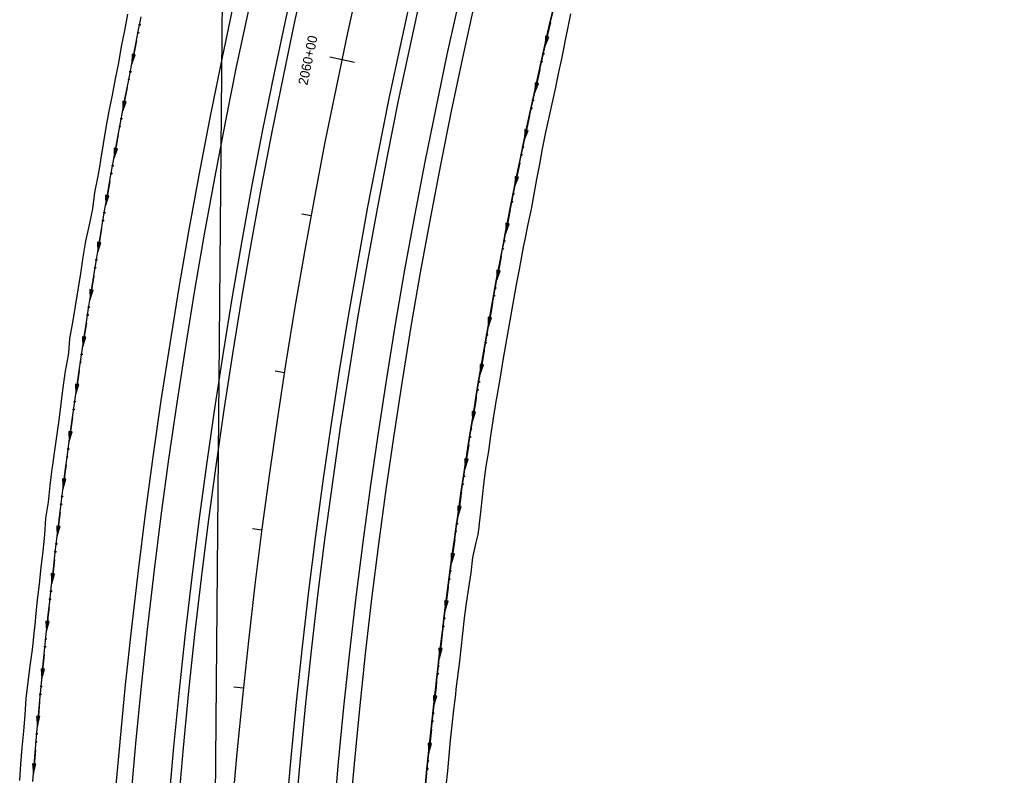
# Model space of a CAD drawing. Extents: x 1611108 to 1749517, y 619561 to 797725.
# Drawn here: x 1713487 to 1714111, y 762566 to 763041 of the extents above; entities that cross this region are included whole.
import ezdxf

# ---------------------------------------------------------------- set-up
doc = ezdxf.new("R2010")
doc.units = 0
for name, color, linetype in [('R_Ditch', 7, 'Continuous'), ('R_Horz Alg', 7, 'Continuous'), ('R_Horz Alg Annot', 7, 'Continuous'), ('R_Horz Alg Stationing', 7, 'Continuous'), ('R_Proposed Const Limits', 7, 'Continuous'), ('R_Proposed Road', 7, 'Continuous')]:
    doc.layers.add(name, color=color, linetype=linetype)

msp = doc.modelspace()

# ---------------------------------------------------------------- linework, layer by layer
at = {"layer": 'R_Ditch'}
for p, q in [((1713817.4, 763030.58), (1713817.11, 763024.49)), ((1713817.11, 763024.49), (1713819.47, 763030.11)), ((1713819.47, 763030.11), (1713817.4, 763030.58)), ((1713557.34, 763019.3), (1713557.21, 763013.21)), ((1713557.21, 763013.21), (1713559.41, 763018.89)), ((1713559.41, 763018.89), (1713557.34, 763019.3)), ((1713810.81, 763001.26), (1713810.56, 762995.18)), ((1713810.56, 762995.18), (1713812.87, 763000.81)), ((1713812.87, 763000.81), (1713810.81, 763001.26)), ((1713551.58, 762989.81), (1713551.5, 762983.72)), ((1713551.5, 762983.72), (1713553.66, 762989.42)), ((1713553.66, 762989.42), (1713551.58, 762989.81)), ((1713804.45, 762971.9), (1713804.24, 762965.81)), ((1713804.24, 762965.81), (1713806.52, 762971.46)), ((1713806.52, 762971.46), (1713804.45, 762971.9)), ((1713546.06, 762960.28), (1713546.02, 762954.19)), ((1713546.02, 762954.19), (1713548.14, 762959.9)), ((1713548.14, 762959.9), (1713546.06, 762960.28)), ((1713798.33, 762942.48), (1713798.17, 762936.39)), ((1713798.17, 762936.39), (1713800.4, 762942.06)), ((1713800.4, 762942.06), (1713798.33, 762942.48)), ((1713542.84, 762930.34), (1713540.75, 762930.71)), ((1713540.75, 762930.71), (1713540.77, 762924.61)), ((1713540.77, 762924.61), (1713542.84, 762930.34)), ((1713792.44, 762913.02), (1713792.34, 762906.93)), ((1713792.34, 762906.93), (1713794.52, 762912.61)), ((1713794.52, 762912.61), (1713792.44, 762913.02)), ((1713537.76, 762900.75), (1713535.68, 762901.09)), ((1713535.68, 762901.09), (1713535.74, 762895)), ((1713535.74, 762895), (1713537.76, 762900.75)), ((1713786.8, 762883.51), (1713786.74, 762877.41)), ((1713786.74, 762877.41), (1713788.88, 762883.12)), ((1713788.88, 762883.12), (1713786.8, 762883.51)), ((1713532.91, 762871.11), (1713530.82, 762871.44)), ((1713530.82, 762871.44), (1713530.93, 762865.35)), ((1713530.93, 762865.35), (1713532.91, 762871.11)), ((1713781.4, 762853.95), (1713781.39, 762847.86)), ((1713781.39, 762847.86), (1713783.48, 762853.58)), ((1713783.48, 762853.58), (1713781.4, 762853.95)), ((1713528.29, 762841.44), (1713526.2, 762841.75)), ((1713526.2, 762841.75), (1713526.35, 762835.66)), ((1713526.35, 762835.66), (1713528.29, 762841.44)), ((1713778.32, 762823.99), (1713776.24, 762824.35)), ((1713776.24, 762824.35), (1713776.27, 762818.26)), ((1713776.27, 762818.26), (1713778.32, 762823.99)), ((1713523.9, 762811.73), (1713521.8, 762812.03)), ((1713521.8, 762812.03), (1713521.99, 762805.94)), ((1713521.99, 762805.94), (1713523.9, 762811.73)), ((1713773.4, 762794.37), (1713771.31, 762794.71)), ((1713771.31, 762794.71), (1713771.4, 762788.62)), ((1713771.4, 762788.62), (1713773.4, 762794.37)), ((1713519.73, 762781.99), (1713517.63, 762782.28)), ((1713517.63, 762782.28), (1713517.87, 762776.19)), ((1713517.87, 762776.19), (1713519.73, 762781.99)), ((1713768.72, 762764.71), (1713766.62, 762765.03)), ((1713766.62, 762765.03), (1713766.77, 762758.94)), ((1713766.77, 762758.94), (1713768.72, 762764.71)), ((1713515.78, 762752.22), (1713513.69, 762752.49)), ((1713513.69, 762752.49), (1713513.97, 762746.4)), ((1713513.97, 762746.4), (1713515.78, 762752.22)), ((1713764.28, 762735.01), (1713762.19, 762735.31)), ((1713762.19, 762735.31), (1713762.38, 762729.22)), ((1713762.38, 762729.22), (1713764.28, 762735.01)), ((1713512.07, 762722.42), (1713509.97, 762722.68)), ((1713509.97, 762722.68), (1713510.3, 762716.59)), ((1713510.3, 762716.59), (1713512.07, 762722.42)), ((1713760.08, 762705.28), (1713757.99, 762705.56)), ((1713757.99, 762705.56), (1713758.23, 762699.47)), ((1713758.23, 762699.47), (1713760.08, 762705.28)), ((1713508.58, 762692.6), (1713506.47, 762692.83)), ((1713506.47, 762692.83), (1713506.85, 762686.75)), ((1713506.85, 762686.75), (1713508.58, 762692.6)), ((1713756.13, 762675.51), (1713754.03, 762675.78)), ((1713754.03, 762675.78), (1713754.32, 762669.69)), ((1713754.32, 762669.69), (1713756.13, 762675.51)), ((1713505.31, 762662.75), (1713503.2, 762662.96)), ((1713503.2, 762662.96), (1713503.63, 762656.89)), ((1713503.63, 762656.89), (1713505.31, 762662.75)), ((1713752.42, 762645.71), (1713750.32, 762645.96)), ((1713750.32, 762645.96), (1713750.65, 762639.88)), ((1713750.65, 762639.88), (1713752.42, 762645.71)), ((1713502.27, 762632.87), (1713500.17, 762633.07)), ((1713500.17, 762633.07), (1713500.64, 762627)), ((1713500.64, 762627), (1713502.27, 762632.87)), ((1713748.95, 762615.88), (1713746.84, 762616.12)), ((1713746.84, 762616.12), (1713747.23, 762610.03)), ((1713747.23, 762610.03), (1713748.95, 762615.88)), ((1713499.46, 762602.97), (1713497.36, 762603.16)), ((1713497.36, 762603.16), (1713497.88, 762597.09)), ((1713497.88, 762597.09), (1713499.46, 762602.97)), ((1713745.72, 762586.03), (1713743.61, 762586.24)), ((1713743.61, 762586.24), (1713744.05, 762580.17)), ((1713744.05, 762580.17), (1713745.72, 762586.03)), ((1713496.88, 762573.05), (1713494.77, 762573.22)), ((1713494.77, 762573.22), (1713495.34, 762567.16)), ((1713495.34, 762567.16), (1713496.88, 762573.05))]:
    msp.add_line(p, q, dxfattribs=at)
for points in [[(1713494.93, 762562.1), (1713495.77, 762572.4), (1713496.63, 762582.7), (1713497.52, 762592.99), (1713498.43, 762603.28), (1713499.37, 762613.57), (1713500.34, 762623.85), (1713501.33, 762634.14), (1713502.36, 762644.42), (1713503.41, 762654.7), (1713504.13, 762661.68), (1713504.48, 762664.97), (1713505.58, 762675.25), (1713506.71, 762685.52), (1713507.87, 762695.79), (1713509.05, 762706.05), (1713510.26, 762716.31), (1713511.5, 762726.57), (1713512.77, 762736.83), (1713514.06, 762747.08), (1713515.37, 762757.33), (1713516.72, 762767.58), (1713518.09, 762777.82), (1713519.49, 762788.06), (1713520.91, 762798.29), (1713522.37, 762808.52), (1713523.85, 762818.75), (1713525.35, 762828.98), (1713526.83, 762838.82), (1713526.88, 762839.2), (1713528.44, 762849.41), (1713530.03, 762859.63), (1713531.64, 762869.84), (1713533.28, 762880.04), (1713534.95, 762890.24), (1713536.64, 762900.44), (1713538.36, 762910.63), (1713540.11, 762920.82), (1713541.88, 762931), (1713543.68, 762941.18), (1713545.51, 762951.35), (1713547.36, 762961.52), (1713549.24, 762971.69), (1713551.14, 762981.85), (1713553.08, 762992), (1713555.04, 763002.15), (1713557.02, 763012.3), (1713559.04, 763022.44), (1713561.08, 763032.57), (1713563.14, 763042.7)], [(1713821.96, 763047.35), (1713819.76, 763037.92), (1713817.66, 763028.8), (1713817.59, 763028.49), (1713815.44, 763019.05), (1713813.56, 763010.68), (1713813.32, 763009.61), (1713811.23, 763000.16), (1713809.15, 762990.7), (1713807.1, 762981.24), (1713805.08, 762971.78), (1713803.08, 762962.3), (1713801.11, 762952.83), (1713799.16, 762943.34), (1713797.24, 762933.86), (1713795.33, 762924.36), (1713793.46, 762914.87), (1713791.61, 762905.36), (1713790.85, 762901.43), (1713789.79, 762895.86), (1713787.99, 762886.34), (1713786.21, 762876.83), (1713784.46, 762867.3), (1713782.74, 762857.78), (1713781.04, 762848.24), (1713779.36, 762838.71), (1713777.71, 762829.17), (1713776.08, 762819.62), (1713774.48, 762810.07), (1713772.91, 762800.52), (1713772.85, 762800.17), (1713771.65, 762792.76), (1713771.36, 762790.96), (1713769.83, 762781.4), (1713768.33, 762771.83), (1713766.85, 762762.26), (1713765.4, 762752.69), (1713763.98, 762743.11), (1713762.58, 762733.53), (1713761.53, 762726.27), (1713761.2, 762723.94), (1713760.56, 762719.38), (1713759.85, 762714.35), (1713758.53, 762704.76), (1713757.23, 762695.16), (1713755.95, 762685.56), (1713754.7, 762675.95), (1713753.48, 762666.35), (1713752.28, 762656.74), (1713751.5, 762650.39), (1713751.1, 762647.12), (1713749.96, 762637.51), (1713749.59, 762634.42), (1713748.83, 762627.89), (1713748.12, 762621.69), (1713747.73, 762618.26), (1713746.66, 762608.64), (1713745.61, 762599.01), (1713744.59, 762589.37), (1713743.59, 762579.74), (1713742.61, 762570.1), (1713741.67, 762560.46)], [(1713742.08, 762560.42), (1713743.03, 762570.06), (1713744, 762579.7), (1713745, 762589.33), (1713746.02, 762598.96), (1713747.07, 762608.59), (1713748.14, 762618.22), (1713748.53, 762621.64), (1713749.24, 762627.84), (1713750, 762634.38), (1713750.37, 762637.46), (1713751.52, 762647.08), (1713752.69, 762656.69), (1713753.89, 762666.3), (1713755.11, 762675.91), (1713756.36, 762685.51), (1713757.64, 762695.11), (1713758.94, 762704.7), (1713760.26, 762714.3), (1713760.97, 762719.33), (1713761.61, 762723.88), (1713761.95, 762726.21), (1713762.99, 762733.47), (1713764.39, 762743.05), (1713765.81, 762752.63), (1713767.27, 762762.2), (1713768.74, 762771.77), (1713770.24, 762781.34), (1713771.77, 762790.9), (1713772.06, 762792.7), (1713773.26, 762800.1), (1713773.32, 762800.45), (1713774.89, 762810.01), (1713776.49, 762819.56), (1713778.12, 762829.1), (1713779.77, 762838.64), (1713781.44, 762848.18), (1713783.14, 762857.7), (1713784.87, 762867.23), (1713786.62, 762876.75), (1713788.39, 762886.27), (1713790.19, 762895.78), (1713791.26, 762901.36), (1713792.02, 762905.29), (1713793.87, 762914.79), (1713795.74, 762924.29), (1713797.64, 762933.78), (1713799.56, 762943.26), (1713801.51, 762952.75), (1713803.49, 762962.22), (1713805.49, 762971.69), (1713807.51, 762981.16), (1713809.56, 762990.62), (1713811.63, 763000.07), (1713813.73, 763009.52), (1713813.97, 763010.59), (1713815.85, 763018.96), (1713818, 763028.4), (1713818.06, 763028.71), (1713820.17, 763037.83), (1713822.36, 763047.26)], [(1713820.46, 763039.11), (1713820.17, 763037.83), (1713818.06, 763028.71), (1713818, 763028.4), (1713817.11, 763024.49)], [(1713820.47, 763039.15), (1713820.46, 763039.11)], [(1713560.14, 763027.92), (1713559.04, 763022.44), (1713557.21, 763013.21)], [(1713560.15, 763027.96), (1713560.14, 763027.92)], [(1713813.79, 763009.82), (1713813.73, 763009.52), (1713811.63, 763000.07), (1713810.56, 762995.18)], [(1713813.8, 763009.86), (1713813.79, 763009.82)], [(1713554.32, 762998.45), (1713553.08, 762992), (1713551.5, 762983.72)], [(1713554.33, 762998.49), (1713554.32, 762998.45)], [(1713807.36, 762980.48), (1713805.49, 762971.69), (1713804.24, 762965.81)], [(1713807.37, 762980.52), (1713807.36, 762980.48)], [(1713548.73, 762968.94), (1713547.36, 762961.52), (1713546.02, 762954.19)], [(1713548.74, 762968.98), (1713548.73, 762968.94)], [(1713801.17, 762951.09), (1713799.56, 762943.26), (1713798.17, 762936.39)], [(1713801.18, 762951.13), (1713801.17, 762951.09)], [(1713543.36, 762939.39), (1713541.88, 762931), (1713540.77, 762924.61)], [(1713543.37, 762939.42), (1713543.36, 762939.39)], [(1713795.22, 762921.65), (1713793.87, 762914.79), (1713792.34, 762906.93)], [(1713795.23, 762921.68), (1713795.22, 762921.65)], [(1713538.22, 762909.79), (1713536.64, 762900.44), (1713535.74, 762895)], [(1713538.22, 762909.83), (1713538.22, 762909.79)], [(1713789.51, 762892.16), (1713788.39, 762886.27), (1713786.74, 762877.41)], [(1713789.51, 762892.19), (1713789.51, 762892.16)], [(1713533.3, 762880.16), (1713533.28, 762880.04), (1713531.64, 762869.84), (1713530.93, 762865.35)], [(1713533.31, 762880.2), (1713533.3, 762880.16)], [(1713784.03, 762862.62), (1713783.14, 762857.7), (1713781.44, 762848.18), (1713781.39, 762847.86)], [(1713784.04, 762862.66), (1713784.03, 762862.62)], [(1713528.61, 762850.49), (1713528.44, 762849.41), (1713526.88, 762839.2), (1713526.83, 762838.82), (1713526.35, 762835.66)], [(1713528.62, 762850.53), (1713528.61, 762850.49)], [(1713778.8, 762833.04), (1713778.12, 762829.1), (1713776.49, 762819.56), (1713776.27, 762818.26)], [(1713778.81, 762833.08), (1713778.8, 762833.04)], [(1713524.14, 762820.79), (1713523.85, 762818.75), (1713522.37, 762808.52), (1713522, 762805.94)], [(1713524.15, 762820.82), (1713524.14, 762820.79)], [(1713773.81, 762803.42), (1713773.32, 762800.45), (1713773.26, 762800.1), (1713772.06, 762792.7), (1713771.77, 762790.9), (1713771.4, 762788.62)], [(1713773.81, 762803.46), (1713773.81, 762803.42)], [(1713519.91, 762791.05), (1713519.49, 762788.06), (1713518.09, 762777.82), (1713517.87, 762776.19)], [(1713519.91, 762791.09), (1713519.91, 762791.05)], [(1713769.05, 762773.76), (1713768.74, 762771.77), (1713767.27, 762762.2), (1713766.77, 762758.94)], [(1713769.06, 762773.8), (1713769.05, 762773.76)], [(1713515.89, 762761.28), (1713515.37, 762757.33), (1713514.06, 762747.08), (1713513.97, 762746.4)], [(1713515.9, 762761.32), (1713515.89, 762761.28)], [(1713764.54, 762744.07), (1713764.39, 762743.05), (1713762.99, 762733.47), (1713762.38, 762729.22)], [(1713764.55, 762744.1), (1713764.54, 762744.07)], [(1713512.11, 762731.48), (1713511.5, 762726.57), (1713510.3, 762716.59)], [(1713512.11, 762731.52), (1713512.11, 762731.48)], [(1713760.27, 762714.33), (1713760.26, 762714.3), (1713758.94, 762704.7), (1713758.23, 762699.47)], [(1713760.27, 762714.37), (1713760.27, 762714.33)], [(1713508.55, 762701.66), (1713507.87, 762695.79), (1713506.85, 762686.75)], [(1713508.55, 762701.69), (1713508.55, 762701.66)], [(1713756.24, 762684.57), (1713755.11, 762675.91), (1713754.32, 762669.69)], [(1713756.25, 762684.6), (1713756.24, 762684.57)], [(1713505.21, 762671.8), (1713504.48, 762664.97), (1713504.13, 762661.68), (1713503.63, 762656.89)], [(1713505.22, 762671.84), (1713505.21, 762671.8)], [(1713752.46, 762654.77), (1713751.52, 762647.08), (1713750.65, 762639.88)], [(1713752.46, 762654.81), (1713752.46, 762654.77)], [(1713502.11, 762641.93), (1713501.33, 762634.14), (1713500.64, 762627)], [(1713502.11, 762641.96), (1713502.11, 762641.93)], [(1713748.91, 762624.94), (1713748.53, 762621.64), (1713748.14, 762618.22), (1713747.23, 762610.03)], [(1713748.91, 762624.98), (1713748.91, 762624.94)], [(1713499.23, 762612.03), (1713498.43, 762603.28), (1713497.88, 762597.09)], [(1713499.23, 762612.06), (1713499.23, 762612.03)], [(1713745.61, 762595.08), (1713745, 762589.33), (1713744.05, 762580.17)], [(1713745.61, 762595.12), (1713745.61, 762595.09)], [(1713496.58, 762582.11), (1713495.77, 762572.4), (1713495.34, 762567.16)], [(1713496.58, 762582.14), (1713496.58, 762582.11)]]:
    msp.add_lwpolyline(points, dxfattribs=at)
for centre in [(1713562.17, 763037.75), (1713561.17, 763032.84), (1713816.03, 763019.6), (1713814.93, 763014.71), (1713556.28, 763008.29), (1713555.31, 763003.38), (1713808.46, 762985.38), (1713809.52, 762990.28), (1713549.68, 762973.87), (1713550.61, 762978.8), (1713803.25, 762960.9), (1713802.23, 762956), (1713545.17, 762949.26), (1713544.28, 762944.32), (1713797.22, 762931.48), (1713796.23, 762926.56), (1713539.95, 762919.67), (1713539.1, 762914.74), (1713791.42, 762902), (1713790.48, 762897.08), (1713534.95, 762890.06), (1713534.15, 762885.11), (1713784.97, 762867.56), (1713785.87, 762872.48), (1713530.19, 762860.4), (1713529.42, 762855.45), (1713780.56, 762842.92), (1713779.69, 762837.99), (1713525.65, 762830.71), (1713524.91, 762825.75), (1713775.48, 762813.31), (1713774.66, 762808.37), (1713521.33, 762800.98), (1713520.63, 762796.02), (1713770.65, 762783.67), (1713769.87, 762778.72), (1713517.24, 762771.22), (1713516.58, 762766.26), (1713765.31, 762749.03), (1713766.06, 762753.98), (1713512.76, 762736.46), (1713513.38, 762741.43), (1713761.7, 762724.26), (1713761, 762719.3), (1713509.75, 762711.62), (1713509.16, 762706.64), (1713757.59, 762694.51), (1713756.94, 762689.54), (1713506.34, 762681.77), (1713505.79, 762676.79), (1713753.73, 762664.72), (1713753.11, 762659.75), (1713503.16, 762651.9), (1713502.65, 762646.92), (1713749.52, 762629.93), (1713750.1, 762634.9), (1713499.73, 762617.02), (1713500.2, 762622.01), (1713746.72, 762605.05), (1713746.18, 762600.07), (1713497.47, 762592.1), (1713497.04, 762587.11), (1713743.58, 762575.18), (1713743.08, 762570.2)]:
    msp.add_circle(centre, 0.375, dxfattribs=at)
at = {"layer": 'R_Horz Alg'}
msp.add_arc((1717426.61, 762226.09), 3819.72, 112.5, 179.5, dxfattribs=at)
at = {"layer": 'R_Horz Alg Annot'}
msp.add_line((1713629.09, 764787.55), (1713607.03, 762259.43), dxfattribs=at)
at = {"layer": 'R_Horz Alg Stationing'}
for points in [[(1713681.63, 763017.66), (1713697.28, 763014.35)], [(1713664.16, 762918.99), (1713670.06, 762917.91)], [(1713647.31, 762820.27), (1713653.24, 762819.33)], [(1713633.05, 762721.13), (1713639, 762720.35)], [(1713621.39, 762621.66), (1713627.36, 762621.04)]]:
    msp.add_lwpolyline(points, dxfattribs=at)
at = {"layer": 'R_Proposed Const Limits'}
for points in [[(1713486.8, 762562.8), (1713487.47, 762573.13), (1713488.31, 762583.45), (1713489.36, 762593.75), (1713490.23, 762604.07), (1713490.8, 762614.41), (1713491.94, 762624.7), (1713493.31, 762634.97), (1713494.72, 762645.23), (1713495.12, 762648.89), (1713495.8, 762655.53), (1713496.59, 762662.52), (1713496.93, 762665.82), (1713497.99, 762676.12), (1713499.09, 762686.41), (1713500.21, 762696.7), (1713501.36, 762706.99), (1713502.54, 762717.28), (1713503.16, 762727.64), (1713504.83, 762737.86), (1713505.78, 762748.18), (1713506.49, 762753.57), (1713507.15, 762758.45), (1713507.49, 762760.94), (1713508.55, 762768.71), (1713509.98, 762778.96), (1713511.44, 762789.21), (1713512.8, 762799.48), (1713514.13, 762809.75), (1713515.6, 762820.01), (1713517.3, 762830.22), (1713517.64, 762832.14), (1713518.15, 762840.18), (1713518.21, 762840.56), (1713520.17, 762850.74), (1713521.87, 762860.95), (1713523.46, 762871.19), (1713525.07, 762881.42), (1713526.63, 762891.66), (1713528.35, 762901.88), (1713530.51, 762912.01), (1713532.64, 762922.15), (1713534, 762932.43), (1713536.03, 762942.59), (1713537.14, 762948.56), (1713537.77, 762952.8), (1713539.38, 762963.04), (1713541.15, 762973.24), (1713543, 762983.44), (1713544.99, 762993.6), (1713547.04, 763003.76), (1713548.97, 763013.93), (1713550.75, 763024.14), (1713552.83, 763034.29), (1713554.66, 763044.49)], [(1713754.88, 762559.26), (1713756.01, 762568.85), (1713756.76, 762578.47), (1713757.7, 762588.08), (1713758.73, 762597.68), (1713759.78, 762607.27), (1713760.87, 762616.86), (1713761.26, 762620.27), (1713761.98, 762626.45), (1713762.87, 762632.95), (1713763.34, 762636.01), (1713764.42, 762645.6), (1713765.41, 762655.2), (1713766.42, 762664.8), (1713767.71, 762674.36), (1713769.2, 762683.9), (1713770.61, 762693.45), (1713771.62, 762703.05), (1713773.8, 762712.49), (1713775.08, 762717.43), (1713775.58, 762721.99), (1713775.84, 762724.31), (1713776.66, 762731.58), (1713777.76, 762741.16), (1713778.88, 762750.75), (1713780.07, 762760.33), (1713781.7, 762769.84), (1713783.06, 762779.39), (1713784.37, 762788.95), (1713784.68, 762790.74), (1713785.93, 762798.11), (1713785.99, 762798.46), (1713787.64, 762807.97), (1713789.21, 762817.49), (1713790.78, 762827.01), (1713792.44, 762836.51), (1713794.18, 762846), (1713795.86, 762855.5), (1713797.51, 762865.01), (1713799.19, 762874.51), (1713800.9, 762884), (1713802.62, 762893.49), (1713803.7, 762899.05), (1713804.51, 762902.95), (1713806.5, 762912.39), (1713808.51, 762921.83), (1713810.24, 762931.32), (1713811.95, 762940.82), (1713813.7, 762950.3), (1713815.46, 762959.79), (1713817.31, 762969.26), (1713819.4, 762978.68), (1713821.5, 762988.09), (1713823.61, 762997.51), (1713825.58, 763006.95), (1713825.81, 763008.03), (1713827.52, 763016.4), (1713829.43, 763025.86), (1713829.5, 763026.16), (1713831.38, 763035.31), (1713833.33, 763044.76)]]:
    msp.add_lwpolyline(points, dxfattribs=at)
at = {"layer": 'R_Proposed Road'}
for radius in [3893.72, 3883.72, 3859.72, 3853.72, 3785.72, 3779.72, 3755.72, 3745.72]:
    msp.add_arc((1717426.61, 762226.09), radius, 112.5, 179.5, dxfattribs=at)

# ---------------------------------------------------------------- texts
at = {"layer": 'R_Horz Alg Stationing'}
msp.add_text('2060+00', height=6, rotation=78.06525, dxfattribs=at).set_placement((1713667.57, 762999.53))

doc.saveas('drawing.dxf')
